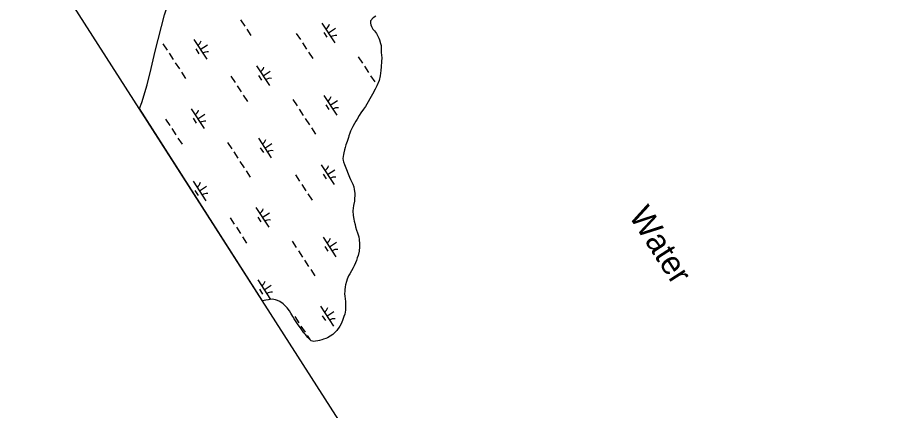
# Model space of a CAD drawing. Extents: x 3945642 to 3966284, y 206476 to 228921.
# Drawn here: x 3949497 to 3951337, y 220977 to 221813 of the extents above; entities that cross this region are included whole.
import ezdxf

# ---------------------------------------------------------------- set-up
doc = ezdxf.new("R2010")
doc.units = 0
for name, color, linetype in [('V-ANNO-NOTE', 7, 'Continuous'), ('V-GRID-FRAM', 7, 'Continuous'), ('V-RIVR-IDEN', 7, 'Continuous'), ('V-TOPO-SHOR', 7, 'Continuous'), ('V-WETL-SWMP', 7, 'Continuous')]:
    doc.layers.add(name, color=color, linetype=linetype)

msp = doc.modelspace()

# ---------------------------------------------------------------- linework, layer by layer
at = {"layer": 'V-GRID-FRAM'}
msp.add_lwpolyline([(3956475, 226502.1), (3964764.2, 213849), (3957669.1, 209282.6), (3949512, 222000.5), (3956475, 226502.1)], dxfattribs=at)
at = {"layer": 'V-TOPO-SHOR'}
msp.add_lwpolyline([(3949756.7, 221619.1), (3949761.5, 221632.2), (3949773.3, 221669.4), (3949781.4, 221704.3), (3949790.5, 221741.6), (3949810.1, 221818.6), (3949823.1, 221856.7), (3949834.1, 221885.6), (3949842, 221911.4), (3949852.3, 221942.6), (3949862.9, 221982.7), (3949870.6, 222012.9), (3949876.7, 222039.2), (3949880.7, 222064.7), (3949884.4, 222090.5), (3949886.9, 222114.9), (3949888, 222138.6), (3949888.9, 222162.8), (3949891.4, 222185.7), (3949893.4, 222203.9), (3949894.2, 222247.6)], dxfattribs=at)
at = {"layer": 'V-WETL-SWMP'}
for p, q in [((3949790.5, 221741.6), (3949810.1, 221818.6)), ((3950260.1, 221815.7), (3950254.1, 221811.9)), ((3949972.2, 221807.9), (3949981, 221794.6)), ((3950145.3, 221801), (3950172.7, 221759.2)), ((3950248.7, 221805.6), (3950248.6, 221801.1)), ((3950248.6, 221801.1), (3950249.4, 221797.5)), ((3950254.1, 221811.9), (3950248.7, 221805.6)), ((3950249.4, 221797.5), (3950250.8, 221793.6)), ((3949985.4, 221787.9), (3949994.1, 221774.5)), ((3950090.6, 221779.2), (3950099.4, 221765.8)), ((3950149.3, 221780.9), (3950155.8, 221770.8)), ((3950159, 221780.1), (3950174, 221789.9)), ((3950250.8, 221793.6), (3950253.9, 221788.1)), ((3950253.9, 221788.1), (3950256.9, 221784.4)), ((3950256.9, 221784.4), (3950261.4, 221778.8)), ((3950261.4, 221778.8), (3950263.6, 221774.9)), ((3949872.6, 221766.1), (3949900, 221724.2)), ((3950103.8, 221759.1), (3950112.5, 221745.7)), ((3950263.6, 221774.9), (3950266.3, 221768.9)), ((3950266.3, 221768.9), (3950267.5, 221765.2)), ((3950267.5, 221765.2), (3950270.1, 221757.6)), ((3949781.4, 221704.3), (3949790.5, 221741.6)), ((3949806.8, 221756.9), (3949815.5, 221743.6)), ((3949876.5, 221746), (3949883.1, 221735.9)), ((3949886.3, 221745.2), (3949901.3, 221755)), ((3950270.1, 221757.6), (3950271, 221753.6)), ((3950271, 221753.6), (3950271.3, 221748.9)), ((3950271.3, 221748.9), (3950271.4, 221744.9)), ((3950271.4, 221744.9), (3950271.3, 221738.2)), ((3949819.9, 221736.9), (3949828.7, 221723.5)), ((3950116.9, 221739), (3950125.7, 221725.6)), ((3950222.6, 221729.3), (3950231.3, 221715.9)), ((3950271.3, 221738.2), (3950271.7, 221732.8)), ((3950271.7, 221732.8), (3950272.4, 221726.8)), ((3950272.4, 221726.8), (3950272.3, 221719.6)), ((3949773.3, 221669.4), (3949781.4, 221704.3)), ((3949833.1, 221716.8), (3949841.8, 221703.4)), ((3950006.2, 221709.8), (3950033.6, 221668)), ((3950235.7, 221709.3), (3950244.5, 221695.9)), ((3950271.3, 221707.7), (3950270.5, 221699.9)), ((3950272.3, 221719.6), (3950271.3, 221707.7)), ((3949846.2, 221696.7), (3949855, 221683.3)), ((3949951.5, 221688), (3949960.2, 221674.6)), ((3950010.1, 221689.7), (3950016.7, 221679.7)), ((3950019.9, 221688.9), (3950034.9, 221698.8)), ((3950248.9, 221689.2), (3950257.6, 221675.8)), ((3950269.5, 221688.6), (3950266.9, 221678.7)), ((3950270.5, 221699.9), (3950269.5, 221688.6)), ((3949761.5, 221632.2), (3949773.3, 221669.4)), ((3949964.6, 221667.9), (3949973.4, 221654.5)), ((3950262.1, 221667.9), (3950258.4, 221660.2)), ((3950262, 221669.1), (3950262.4, 221668.6)), ((3950266.9, 221678.7), (3950262.1, 221667.9)), ((3950252.9, 221649.9), (3950247.3, 221640.1)), ((3950258.4, 221660.2), (3950252.9, 221649.9)), ((3949756.7, 221619.1), (3949761.5, 221632.2)), ((3949977.8, 221647.9), (3949986.5, 221634.5)), ((3950083.4, 221638.2), (3950092.2, 221624.8)), ((3950149.2, 221647.3), (3950176.6, 221605.5)), ((3950162.9, 221626.4), (3950178, 221636.3)), ((3950243.6, 221633.7), (3950237.8, 221623.9)), ((3950247.3, 221640.1), (3950243.6, 221633.7)), ((3950018.6, 221210.7), (3949756.7, 221619.1)), ((3949867, 221618.7), (3949894.4, 221576.9)), ((3950096.6, 221618.1), (3950105.4, 221604.7)), ((3950153.2, 221627.2), (3950159.8, 221617.1)), ((3950233.8, 221618.2), (3950228, 221609.9)), ((3950237.8, 221623.9), (3950233.8, 221618.2)), ((3949812.3, 221596.9), (3949821.1, 221583.5)), ((3949871, 221598.6), (3949877.5, 221588.5)), ((3949880.7, 221597.8), (3949895.8, 221607.6)), ((3950109.7, 221598), (3950118.5, 221584.6)), ((3950220.1, 221597), (3950217.2, 221592.3)), ((3950224.6, 221604.6), (3950220.1, 221597)), ((3950228, 221609.9), (3950224.6, 221604.6)), ((3949825.5, 221576.8), (3949834.2, 221563.4)), ((3950122.9, 221578), (3950131.7, 221564.6)), ((3950208.8, 221577.2), (3950205.7, 221571)), ((3950210.9, 221581.4), (3950208.8, 221577.2)), ((3950214.6, 221587.8), (3950210.9, 221581.4)), ((3950217.2, 221592.3), (3950214.6, 221587.8)), ((3949838.6, 221556.7), (3949847.4, 221543.3)), ((3950201.5, 221557.7), (3950200.2, 221553.6)), ((3950202.5, 221561.1), (3950201.5, 221557.7)), ((3950204.3, 221567), (3950202.5, 221561.1)), ((3950205.7, 221571), (3950204.3, 221567)), ((3949944.3, 221547), (3949953.1, 221533.6)), ((3950010.1, 221556.2), (3950037.5, 221514.3)), ((3950023.8, 221535.2), (3950038.8, 221545.1)), ((3950196.4, 221542), (3950194.4, 221536.2)), ((3950197.5, 221545.5), (3950196.4, 221542)), ((3950198.9, 221549.3), (3950197.5, 221545.5)), ((3950200.2, 221553.6), (3950198.9, 221549.3)), ((3949957.4, 221527), (3949966.2, 221513.6)), ((3950014, 221536), (3950020.6, 221526)), ((3950190.8, 221521.3), (3950189.6, 221513.2)), ((3950191.9, 221525.4), (3950190.8, 221521.3)), ((3950193.2, 221531.7), (3950191.9, 221525.4)), ((3950194.4, 221536.2), (3950193.2, 221531.7)), ((3949970.6, 221506.9), (3949979.4, 221493.5)), ((3950189.6, 221513.2), (3950190.4, 221509.1)), ((3950190.4, 221509.1), (3950191.2, 221506.1)), ((3950191.2, 221506.1), (3950193.4, 221500.6)), ((3949983.8, 221486.8), (3949992.5, 221473.4)), ((3950143.7, 221499.9), (3950171.1, 221458.1)), ((3950157.4, 221479), (3950172.4, 221488.9)), ((3950193.4, 221500.6), (3950197.8, 221489.7)), ((3950197.8, 221489.7), (3950201.3, 221480.3)), ((3949871, 221465), (3949898.3, 221423.2)), ((3950089, 221478.1), (3950097.8, 221464.7)), ((3950147.6, 221479.8), (3950154.2, 221469.8)), ((3950201.3, 221480.3), (3950204.1, 221473.3)), ((3950204.1, 221473.3), (3950205.8, 221468.8)), ((3950205.8, 221468.8), (3950208.8, 221462.5)), ((3949884.7, 221444.1), (3949899.7, 221454)), ((3950102.1, 221458), (3950110.9, 221444.6)), ((3950208.8, 221462.5), (3950210.7, 221458.6)), ((3950210.7, 221458.6), (3950212.8, 221452.9)), ((3950212.8, 221452.9), (3950214, 221447.5)), ((3950214, 221447.5), (3950214.7, 221443.9)), ((3949874.9, 221444.9), (3949881.5, 221434.8)), ((3950115.3, 221437.9), (3950124.1, 221424.6)), ((3950214.6, 221427.8), (3950214.2, 221422.2)), ((3950215.5, 221434.5), (3950214.6, 221427.8)), ((3950214.7, 221443.9), (3950215.3, 221438.5)), ((3950215.3, 221438.5), (3950215.5, 221434.5)), ((3950212.7, 221413.1), (3950211.8, 221407.3)), ((3950214.2, 221422.2), (3950212.7, 221413.1)), ((3950004.5, 221408.8), (3950031.9, 221367)), ((3950018.2, 221387.9), (3950033.3, 221397.7)), ((3950211.8, 221407.3), (3950211.2, 221401.9)), ((3950211.2, 221401.9), (3950211.7, 221391.8)), ((3950211.7, 221391.8), (3950212.9, 221384.4)), ((3949949.8, 221386.9), (3949958.6, 221373.6)), ((3950008.5, 221388.7), (3950015.1, 221378.6)), ((3950212.9, 221384.4), (3950214, 221379.7)), ((3950214, 221379.7), (3950215.6, 221372.6)), ((3950215.6, 221372.6), (3950216.7, 221368)), ((3949963, 221366.9), (3949971.8, 221353.5)), ((3950216.7, 221368), (3950219, 221360.4)), ((3950219, 221360.4), (3950220.9, 221354.8)), ((3950220.9, 221354.8), (3950223.6, 221346.3)), ((3949976.1, 221346.8), (3949984.9, 221333.4)), ((3950081.8, 221337.1), (3950090.6, 221323.7)), ((3950147.6, 221346.2), (3950175, 221304.4)), ((3950223.6, 221346.3), (3950224.7, 221340.7)), ((3950224.7, 221340.7), (3950225.3, 221331.9)), ((3950151.6, 221326.1), (3950158.1, 221316.1)), ((3950161.3, 221325.3), (3950176.4, 221335.2)), ((3950225.1, 221325.5), (3950224.3, 221316.1)), ((3950225.3, 221331.9), (3950225.1, 221325.5)), ((3950095, 221317), (3950103.7, 221303.7)), ((3950220.3, 221301.6), (3950218.5, 221296.3)), ((3950222.1, 221307.2), (3950220.3, 221301.6)), ((3950224.3, 221316.1), (3950222.1, 221307.2)), ((3950108.1, 221297), (3950116.9, 221283.6)), ((3950211.9, 221280.8), (3950208.4, 221274.6)), ((3950213.8, 221285), (3950211.9, 221280.8)), ((3950216.7, 221291.5), (3950213.8, 221285)), ((3950218.5, 221296.3), (3950216.7, 221291.5)), ((3950121.3, 221276.9), (3950130, 221263.5)), ((3950201.9, 221263.7), (3950199.2, 221256.5)), ((3950204.5, 221268.2), (3950201.9, 221263.7)), ((3950208.4, 221274.6), (3950204.5, 221268.2)), ((3950008.5, 221255.1), (3950035.8, 221213.3)), ((3950022.2, 221234.2), (3950037.2, 221244)), ((3950195.4, 221244.3), (3950194.5, 221240.1)), ((3950197.4, 221251.6), (3950195.4, 221244.3)), ((3950199.2, 221256.5), (3950197.4, 221251.6)), ((3950012.4, 221235), (3950019, 221224.9)), ((3950193.6, 221230.3), (3950193.5, 221226.4)), ((3950193.5, 221226.4), (3950194.1, 221219.8)), ((3950193.9, 221234), (3950193.6, 221230.3)), ((3950194.5, 221240.1), (3950193.9, 221234)), ((3950022.2, 221211.1), (3950018.6, 221210.7)), ((3950025.9, 221211.6), (3950022.2, 221211.1)), ((3950031.2, 221212.6), (3950025.9, 221211.6)), ((3950034.6, 221213.1), (3950031.2, 221212.6)), ((3950039.1, 221213.9), (3950034.6, 221213.1)), ((3950046.6, 221212.8), (3950039.1, 221213.9)), ((3950050.9, 221211.5), (3950046.6, 221212.8)), ((3950055.9, 221209.2), (3950050.9, 221211.5)), ((3950062.4, 221204.3), (3950055.9, 221209.2)), ((3950194.1, 221219.8), (3950194.8, 221215.4)), ((3950194.8, 221215.4), (3950195.4, 221208.3)), ((3950195.4, 221208.3), (3950195.6, 221203.5)), ((3950065.7, 221201.3), (3950062.4, 221204.3)), ((3950071, 221195.9), (3950065.7, 221201.3)), ((3950076.3, 221189.3), (3950071, 221195.9)), ((3950079.3, 221184.5), (3950076.3, 221189.3)), ((3950142.1, 221198.9), (3950169.5, 221157)), ((3950195.1, 221190.6), (3950193.7, 221182.4)), ((3950195.7, 221195.9), (3950195.1, 221190.6)), ((3950195.6, 221203.5), (3950195.7, 221195.9)), ((3950083.1, 221177.5), (3950079.3, 221184.5)), ((3950086, 221172.5), (3950083.1, 221177.5)), ((3950090.3, 221165.8), (3950086, 221172.5)), ((3950087.4, 221177), (3950096.1, 221163.6)), ((3950146, 221178.7), (3950152.6, 221168.7)), ((3950155.8, 221177.9), (3950170.8, 221187.8)), ((3950192.1, 221177.1), (3950189, 221168.7)), ((3950193.7, 221182.4), (3950192.1, 221177.1)), ((3950092.9, 221161.8), (3950090.3, 221165.8)), ((3950096.8, 221156.7), (3950092.9, 221161.8)), ((3950099.6, 221153.1), (3950096.8, 221156.7)), ((3950102.3, 221148.8), (3950099.6, 221153.1)), ((3950100.5, 221156.9), (3950109.3, 221143.6)), ((3950183, 221156.4), (3950176.9, 221147.4)), ((3950185.8, 221161.3), (3950183, 221156.4)), ((3950189, 221168.7), (3950185.8, 221161.3)), ((3950106.8, 221142.5), (3950102.3, 221148.8)), ((3950109.9, 221138.6), (3950106.8, 221142.5)), ((3950114.9, 221132.8), (3950109.9, 221138.6)), ((3950113.7, 221136.9), (3950119.1, 221128.6)), ((3950162.5, 221135.1), (3950157.3, 221132.2)), ((3950168.1, 221138.8), (3950162.5, 221135.1)), ((3950176.9, 221147.4), (3950168.1, 221138.8)), ((3950118.2, 221129.4), (3950114.9, 221132.8)), ((3950122.3, 221125.7), (3950118.2, 221129.4)), ((3950128.3, 221124), (3950122.3, 221125.7)), ((3950131.4, 221124.6), (3950128.3, 221124)), ((3950136.2, 221125.5), (3950131.4, 221124.6)), ((3950139.9, 221126.4), (3950136.2, 221125.5)), ((3950145.1, 221127.8), (3950139.9, 221126.4)), ((3950148.5, 221128.9), (3950145.1, 221127.8)), ((3950153.6, 221130.7), (3950148.5, 221128.9)), ((3950157.3, 221132.2), (3950153.6, 221130.7))]:
    msp.add_line(p, q, dxfattribs=at)
for centre, start, end in [((3950144.1, 221803.3), 302.4575, 344.0011), ((3949871.3, 221768.4), 302.4575, 344.0011), ((3950174.3, 221757.1), 82.4574, 124.0011), ((3949901.6, 221722.2), 82.4574, 124.0011), ((3950004.9, 221712.2), 302.4575, 344.0011), ((3950035.2, 221666), 82.4574, 124.0011), ((3950148, 221649.6), 302.4575, 344.0011), ((3949865.8, 221621), 302.4575, 344.0011), ((3950178.3, 221603.4), 82.4574, 124.0011), ((3949896.1, 221574.8), 82.4574, 124.0011), ((3950008.9, 221558.5), 302.4575, 344.0011), ((3950039.1, 221512.3), 82.4574, 124.0011), ((3950142.4, 221502.3), 302.4575, 344.0011), ((3950172.7, 221456), 82.4574, 124.0011), ((3949869.7, 221467.3), 302.4575, 344.0011), ((3949900, 221421.1), 82.4574, 124.0011), ((3950003.3, 221411.1), 302.4575, 344.0011), ((3950033.6, 221364.9), 82.4574, 124.0011), ((3950146.4, 221348.6), 302.4575, 344.0011), ((3950176.6, 221302.3), 82.4574, 124.0011), ((3950007.2, 221257.4), 302.4575, 344.0011), ((3950037.5, 221211.2), 82.4574, 124.0011), ((3950140.8, 221201.2), 302.4575, 344.0011), ((3950171.1, 221155), 82.4574, 124.0011)]:
    msp.add_arc(centre, 17.6, start, end, dxfattribs=at)

# ---------------------------------------------------------------- texts
at = {"layer": 'V-ANNO-NOTE'}
for s, p in [('All elevations are expressed in feet and refer to North American Vertical Datum of 1988.', (3948488.1, 221618.9)), ('Contours below Low Water Reference Plane are expressed in feet at 5 and 10 ft. intervals.', (3948418.4, 221573.2))]:
    msp.add_text(s, height=41.5, rotation=303.2293, dxfattribs=at).set_placement(p)
at = {"layer": 'V-RIVR-IDEN'}
msp.add_text('Water', height=50, rotation=302.6757, dxfattribs=at).set_placement((3950797.2, 221391.4))

doc.saveas('drawing.dxf')
